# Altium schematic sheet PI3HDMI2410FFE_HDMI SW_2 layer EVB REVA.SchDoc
size 431 x 279 mm
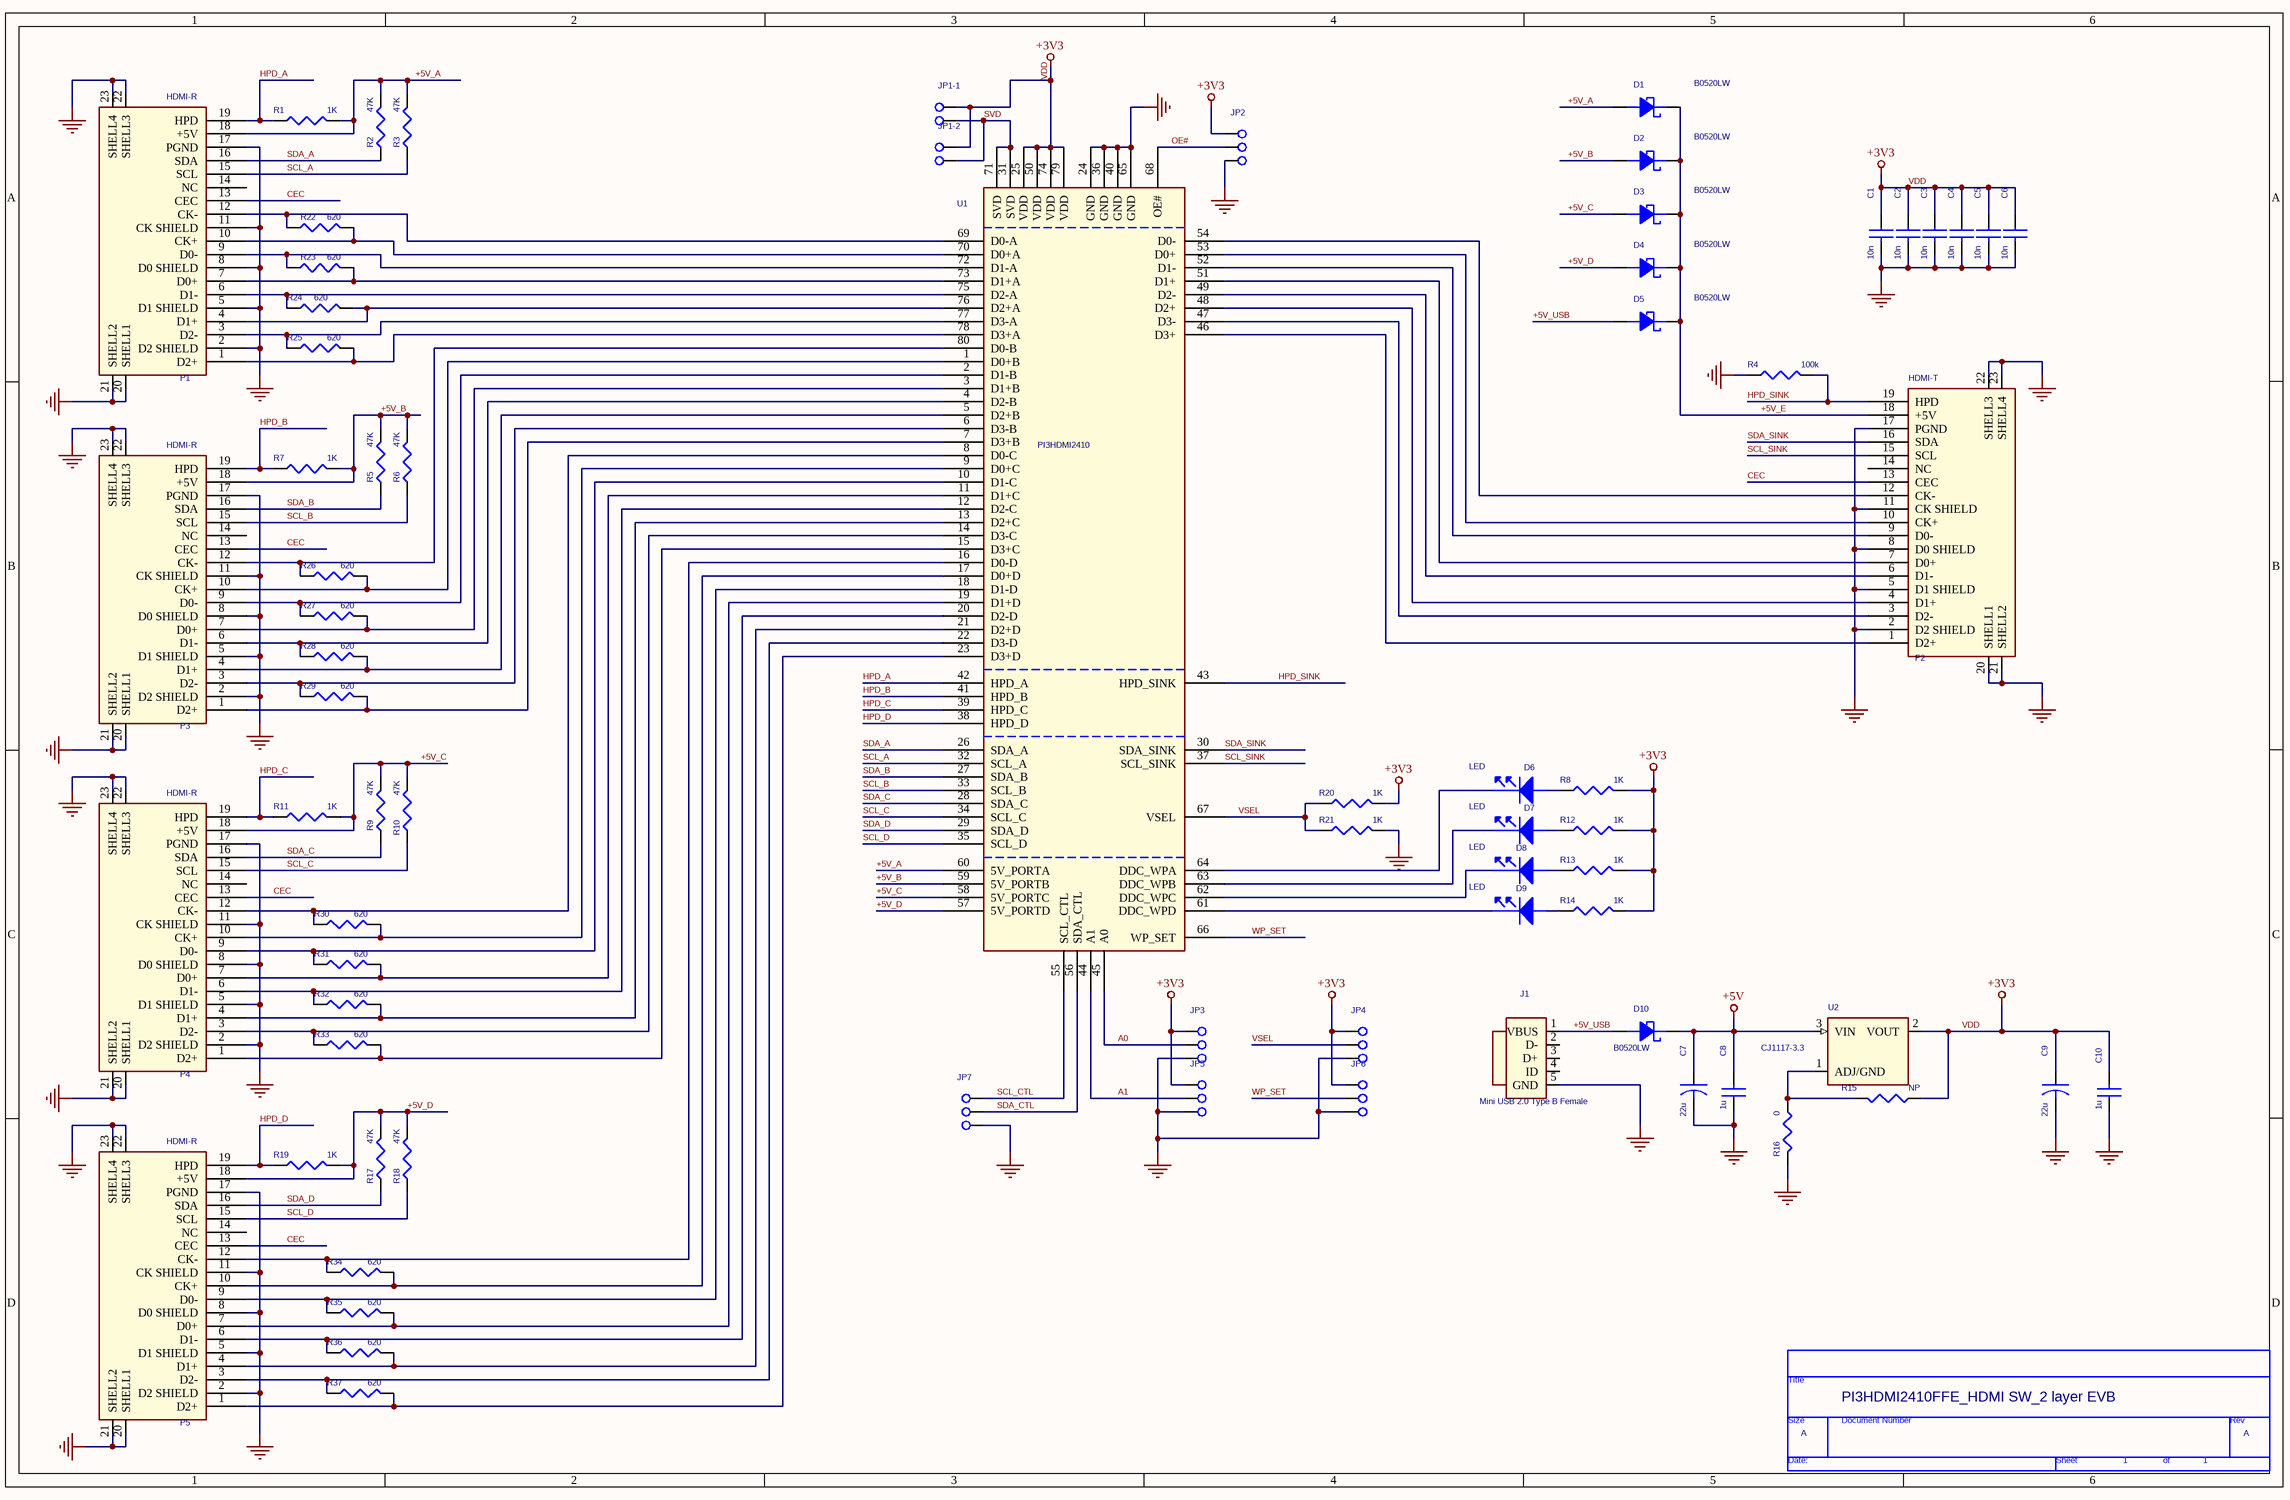
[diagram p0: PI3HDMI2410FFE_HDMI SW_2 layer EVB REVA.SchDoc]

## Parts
*  RevCode: A  Title: PI3HDMI2410FFE_HDMI SW_2 layer EVB  Page Number: 1  (hidden comment: TitleBlock0)  (graphical)
C1  10n  [CAP@CC_0402]
C2  10n  [CAP@CC_0402]
C3  10n  [CAP@CC_0402]
C4  10n  [CAP@CC_0402]
C5  10n  [CAP@CC_0402]
C6  10n  [CAP@CC_0402]
C7  22u  [CAP@CT_3528]
C8  1u  [CAP@CC_0805]
C9  22u  [CAP@CT_3528]
C10  1u  [CAP@CC_0805]
D1  B0520LW  [D@SOD-123]
D2  B0520LW  [D@SOD-123]
D3  B0520LW  [D@SOD-123]
D4  B0520LW  [D@SOD-123]
D5  B0520LW  [D@SOD-123]
D6  LED
D7  LED
D8  LED
D9  LED
D10  B0520LW  [D@SOD-123]
J1  Mini USB 2.0 Type B Female  [USB_B_MINI@USB_B_MINI]
JP1-1  CON 2  [PLUG-2PIN@2PIN-100]  (value not drawn)
JP1-2  CON 2  [PLUG-2PIN@2PIN-100]  (value not drawn)
JP2  CON 3  [PLUG-3PIN@3PIN-100]  (value not drawn)
JP3  CON 3  [PLUG-3PIN@3PIN-100]  (value not drawn)
JP4  CON 3  [PLUG-3PIN@3PIN-100]  (value not drawn)
JP5  CON 3  [PLUG-3PIN@3PIN-100]  (value not drawn)
JP6  CON 3  [PLUG-3PIN@3PIN-100]  (value not drawn)
JP7  CON 3  [PLUG-3PIN@3PIN-100]  (value not drawn)
P1  HDMI-R  [HDMI_R@HDMI_R]
P2  HDMI-T  [HDMI_T@HDMI_T]
P3  HDMI-R  [HDMI_R@HDMI_R]
P4  HDMI-R  [HDMI_R@HDMI_R]
P5  HDMI-R  [HDMI_R@HDMI_R]
R1  1K  [RES@R_0402]
R2  47K  [RES@R_0402]
R3  47K  [RES@R_0402]
R4  100k  [RES@R_0402]
R5  47K  [RES@R_0402]
R6  47K  [RES@R_0402]
R7  1K  [RES@R_0402]
R8  1K  [RES@R_0402]
R9  47K  [RES@R_0402]
R10  47K  [RES@R_0402]
R11  1K  [RES@R_0402]
R12  1K  [RES@R_0402]
R13  1K  [RES@R_0402]
R14  1K  [RES@R_0402]
R15  NP  [RES@R_0402]
R16  0  [RES@R_0402]
R17  47K  [RES@R_0402]
R18  47K  [RES@R_0402]
R19  1K  [RES@R_0402]
R20  1K  [RES@R_0402]
R21  1K  [RES@R_0402]
R22  620  [R_0402]
R23  620  [R_0402]
R24  620  [R_0402]
R25  620  [R_0402]
R26  620  [R_0402]
R27  620  [R_0402]
R28  620  [R_0402]
R29  620  [R_0402]
R30  620  [R_0402]
R31  620  [R_0402]
R32  620  [R_0402]
R33  620  [R_0402]
R34  620  [R_0402]
R35  620  [R_0402]
R36  620  [R_0402]
R37  620  [R_0402]
U1  PI3HDMI2410  [ZF56]
U2  CJ1117-3.3  [Pow_SOT_89]

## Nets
+5V: C7.1 C8.2 D10.2(CATHODE) U2.3(VIN)
GND: C1.2 C2.2 C3.2 C4.2 C5.2 C6.2 C7.2 C8.1 C9.2 C10.1 J1.5(GND) JP2.3 JP3.3 JP4.3 JP5.3 JP6.3 JP7.3 P1.2(D2_SHIELD) P1.5(D1_SHIELD) P1.8(D0_SHIELD) P1.11(CK_SHIELD) P1.17(PGND) P1.20(SHELL1) P1.21(SHELL2) P1.22(SHELL3) P1.23(SHELL4) P2.2(D2_SHIELD) P2.5(D1_SHIELD) P2.8(D0_SHIELD) P2.11(CK_SHIELD) P2.17(PGND) P2.20(SHELL1) P2.21(SHELL2) P2.22(SHELL3) P2.23(SHELL4) P3.2(D2_SHIELD) P3.5(D1_SHIELD) P3.8(D0_SHIELD) P3.11(CK_SHIELD) P3.17(PGND) P3.20(SHELL1) P3.21(SHELL2) P3.22(SHELL3) P3.23(SHELL4) P4.2(D2_SHIELD) P4.5(D1_SHIELD) P4.8(D0_SHIELD) P4.11(CK_SHIELD) P4.17(PGND) P4.20(SHELL1) P4.21(SHELL2) P4.22(SHELL3) P4.23(SHELL4) P5.2(D2_SHIELD) P5.5(D1_SHIELD) P5.8(D0_SHIELD) P5.11(CK_SHIELD) P5.17(PGND) P5.20(SHELL1) P5.21(SHELL2) P5.22(SHELL3) P5.23(SHELL4) R4.1 R16.2 R21.2 U1.24(GND) U1.36(GND) U1.40(GND) U1.65(GND)
VDD: C1.1 C2.1 C3.1 C4.1 C5.1 C6.1 C9.1 C10.2 JP1-1.1 JP1-2.1 JP2.1 JP3.1 JP4.1 JP5.1 JP6.1 R8.2 R12.2 R13.2 R14.2 R15.2 R20.2 U1.25(VDD) U1.50(VDD) U1.74(VDD) U1.79(VDD) U2.2(VOUT)  [also labelled +3V3]
+5V_A: D1.1(ANODE) P1.18(+5V) R1.2 R2.1 R3.1 U1.60(5V_PORTA)
+5V_B: D2.1(ANODE) P3.18(+5V) R5.1 R6.1 R7.2 U1.59(5V_PORTB)
+5V_C: D3.1(ANODE) P4.18(+5V) R9.1 R10.1 R11.2 U1.58(5V_PORTC)
+5V_D: D4.1(ANODE) P5.18(+5V) R17.1 R18.1 R19.2 U1.57(5V_PORTD)
+5V_E: D1.2(CATHODE) D2.2(CATHODE) D3.2(CATHODE) D4.2(CATHODE) D5.2(CATHODE) P2.18(+5V)
+5V_USB: D5.1(ANODE) D10.1(ANODE) J1.1(VBUS)
A0: JP3.2 U1.45(A0)
A1: JP5.2 U1.44(A1)
CEC: P1.13(CEC) P2.13(CEC) P3.13(CEC) P4.13(CEC) P5.13(CEC)
HPD_A: P1.19(HPD) R1.1 U1.42(HPD_A)
HPD_B: P3.19(HPD) R7.1 U1.41(HPD_B)
HPD_C: P4.19(HPD) R11.1 U1.39(HPD_C)
HPD_D: P5.19(HPD) R19.1 U1.38(HPD_D)
HPD_SINK: P2.19(HPD) R4.2 U1.43(HPD_SINK)
OE#: JP2.2 U1.68(OE#)
SCL_A: P1.15(SCL) R3.2 U1.32(SCL_A)
SCL_B: P3.15(SCL) R6.2 U1.33(SCL_B)
SCL_C: P4.15(SCL) R10.2 U1.34(SCL_C)
SCL_CTL: JP7.1 U1.55(SCL_CTL)
SCL_D: P5.15(SCL) R18.2 U1.35(SCL_D)
SCL_SINK: P2.15(SCL) U1.37(SCL_SINK)
SDA_A: P1.16(SDA) R2.2 U1.26(SDA_A)
SDA_B: P3.16(SDA) R5.2 U1.27(SDA_B)
SDA_C: P4.16(SDA) R9.2 U1.28(SDA_C)
SDA_CTL: JP7.2 U1.56(SDA_CTL)
SDA_D: P5.16(SDA) R17.2 U1.29(SDA_D)
SDA_SINK: P2.16(SDA) U1.30(SDA_SINK)
SVD: JP1-1.2 JP1-2.2 U1.31(SVD) U1.71(SVD)
VSEL: JP4.2 R20.1 R21.1 U1.67(VSEL)
WP_SET: JP6.2 U1.66(WP_SET)
NetD6_1: D6.1(ANODE) R8.1
NetD6_2: D6.2(CATHODE) U1.64(DDC_WPA)
NetD7_1: D7.1(ANODE) R12.1
NetD7_2: D7.2(CATHODE) U1.63(DDC_WPB)
NetD8_1: D8.1(ANODE) R13.1
NetD8_2: D8.2(CATHODE) U1.62(DDC_WPC)
NetD9_1: D9.1(ANODE) R14.1
NetD9_2: D9.2(CATHODE) U1.61(DDC_WPD)
NetP1_1: P1.1(D2+) R25.2 U1.78(D3+A)
NetP1_3: P1.3(D2-) R25.1 U1.77(D3-A)
NetP1_4: P1.4(D1+) R24.2 U1.76(D2+A)
NetP1_6: P1.6(D1-) R24.1 U1.75(D2-A)
NetP1_7: P1.7(D0+) R23.2 U1.73(D1+A)
NetP1_9: P1.9(D0-) R23.1 U1.72(D1-A)
NetP1_10: P1.10(CK+) R22.2 U1.70(D0+A)
NetP1_12: P1.12(CK-) R22.1 U1.69(D0-A)
NetP2_1: P2.1(D2+) U1.46(D3+)
NetP2_3: P2.3(D2-) U1.47(D3-)
NetP2_4: P2.4(D1+) U1.48(D2+)
NetP2_6: P2.6(D1-) U1.49(D2-)
NetP2_7: P2.7(D0+) U1.51(D1+)
NetP2_9: P2.9(D0-) U1.52(D1-)
NetP2_10: P2.10(CK+) U1.53(D0+)
NetP2_12: P2.12(CK-) U1.54(D0-)
NetP3_1: P3.1(D2+) R29.2 U1.7(D3+B)
NetP3_3: P3.3(D2-) R29.1 U1.6(D3-B)
NetP3_4: P3.4(D1+) R28.2 U1.5(D2+B)
NetP3_6: P3.6(D1-) R28.1 U1.4(D2-B)
NetP3_7: P3.7(D0+) R27.2 U1.3(D1+B)
NetP3_9: P3.9(D0-) R27.1 U1.2(D1-B)
NetP3_10: P3.10(CK+) R26.2 U1.1(D0+B)
NetP3_12: P3.12(CK-) R26.1 U1.80(D0-B)
NetP4_1: P4.1(D2+) R33.2 U1.15(D3+C)
NetP4_3: P4.3(D2-) R33.1 U1.14(D3-C)
NetP4_4: P4.4(D1+) R32.2 U1.13(D2+C)
NetP4_6: P4.6(D1-) R32.1 U1.12(D2-C)
NetP4_7: P4.7(D0+) R31.2 U1.11(D1+C)
NetP4_9: P4.9(D0-) R31.1 U1.10(D1-C)
NetP4_10: P4.10(CK+) R30.2 U1.9(D0+C)
NetP4_12: P4.12(CK-) R30.1 U1.8(D0-C)
NetP5_1: P5.1(D2+) R37.2 U1.23(D3+D)
NetP5_3: P5.3(D2-) R37.1 U1.22(D3-D)
NetP5_4: P5.4(D1+) R36.2 U1.21(D2+D)
NetP5_6: P5.6(D1-) R36.1 U1.20(D2-D)
NetP5_7: P5.7(D0+) R35.2 U1.19(D1+D)
NetP5_9: P5.9(D0-) R35.1 U1.18(D1-D)
NetP5_10: P5.10(CK+) R34.2 U1.17(D0+D)
NetP5_12: P5.12(CK-) R34.1 U1.16(D0-D)
NetR15_1: R15.1 R16.1 U2.1(ADJ/GND)

Not connected (* = marked no-connect by the designer): J1 2(D-) 3(D+) 4(ID); P1 14(NC); P2 14(NC); P3 14(NC); P4 14(NC); P5 14(NC)

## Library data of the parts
C1-C6 C8 C10 = CAP NP
C7 C9 = CAP
D1-D5 D10 = Diode B0520LW
J1 = USB 2_0.0 Mini B Female
P1-P5 = CON HDMI19_A pin mame
R1-R21 = R
R22-R37 = R_0402
U2 = Pow_LDO_3.3V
